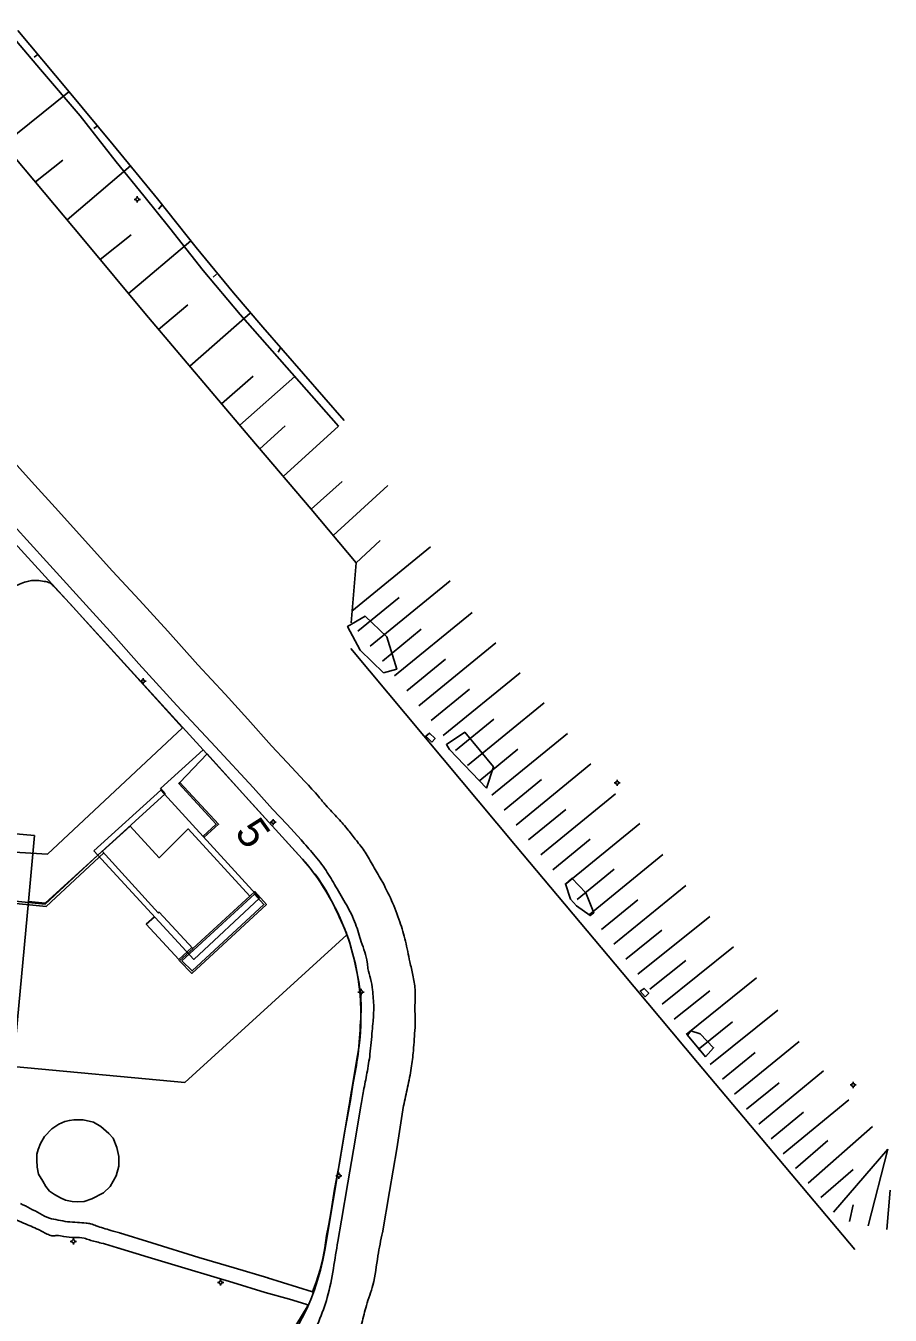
# Model space of a CAD drawing. Extents: x 1517229 to 1518128, y 6494851 to 6495271.
# Drawn here: x 1518015.9 to 1518128.2, y 6495054.4 to 6495221.8 of the extents above; entities that cross this region are included whole.
import ezdxf

# ---------------------------------------------------------------- set-up
doc = ezdxf.new("R2010")
doc.units = 0
doc.layers.add('Karta', color=7, linetype='Continuous')

msp = doc.modelspace()

# ---------------------------------------------------------------- linework, layer by layer
at = {"layer": 'Karta'}
for p, q in [((1518017.51, 6495218.07), (1518017.02, 6495217.73)), ((1518013.08, 6495206.44), (1518021.52, 6495213.26)), ((1518025.24, 6495208.83), (1518024.78, 6495208.5)), ((1518017.18, 6495201.54), (1518020.75, 6495204.36)), ((1518021.31, 6495196.6), (1518029.55, 6495203.63)), ((1518030.22, 6495199.28), (1518030.02, 6495199.28)), ((1518030.42, 6495199.48), (1518030.42, 6495199.68)), ((1518030.42, 6495199.08), (1518030.42, 6495198.88)), ((1518030.62, 6495199.28), (1518030.82, 6495199.28)), ((1518033.67, 6495198.57), (1518033.2, 6495198.02)), ((1518025.58, 6495191.49), (1518029.61, 6495194.69)), ((1518029.27, 6495187.04), (1518037.39, 6495193.88)), ((1518040.71, 6495189.56), (1518040.3, 6495189.16)), ((1518033.2, 6495182.37), (1518036.97, 6495185.57)), ((1518037.25, 6495177.6), (1518045.09, 6495184.52)), ((1518049, 6495179.92), (1518048.73, 6495179.42)), ((1518041.38, 6495172.72), (1518045.47, 6495176.34)), ((1518043.74, 6495169.94), (1518050.87, 6495176.26)), ((1518046.33, 6495166.89), (1518049.63, 6495169.88)), ((1518049.39, 6495163.29), (1518056.54, 6495169.83)), ((1518052.99, 6495159.05), (1518057.04, 6495162.64)), ((1518055.85, 6495155.65), (1518062.97, 6495162.11)), ((1518012.65, 6495156.65), (1518038.97, 6495127.79)), ((1518058.31, 6495145.79), (1518068.53, 6495154.15)), ((1518058.84, 6495152.1), (1518061.96, 6495155)), ((1518060.68, 6495141.26), (1518071.05, 6495149.75)), ((1518059.09, 6495143.2), (1518064.45, 6495147.58)), ((1518063.84, 6495137.39), (1518073.91, 6495145.63)), ((1518024.03, 6495144.16), (1518036.28, 6495130.66)), ((1518062.26, 6495139.33), (1518067.31, 6495143.46)), ((1518067, 6495133.52), (1518077.02, 6495141.71)), ((1518079.55, 6495115.38), (1518058.16, 6495140.96)), ((1518065.42, 6495135.46), (1518070.44, 6495139.56)), ((1518030.97, 6495136.71), (1518030.77, 6495136.71)), ((1518031.17, 6495136.91), (1518031.17, 6495137.11)), ((1518031.37, 6495136.71), (1518031.57, 6495136.71)), ((1518070.17, 6495129.65), (1518080.15, 6495137.81)), ((1518031.17, 6495136.51), (1518031.17, 6495136.31)), ((1518068.59, 6495131.59), (1518073.59, 6495135.68)), ((1518073.33, 6495125.78), (1518083.29, 6495133.92)), ((1518071.75, 6495127.72), (1518076.74, 6495131.79)), ((1518076.5, 6495121.91), (1518086.31, 6495129.93)), ((1518033.46, 6495122.76), (1518038.97, 6495127.79)), ((1518039.48, 6495127.28), (1518035.97, 6495123.55)), ((1518038.97, 6495127.79), (1518051.38, 6495114.18)), ((1518038.97, 6495127.79), (1518051.38, 6495114.18)), ((1518074.92, 6495123.84), (1518079.86, 6495127.89)), ((1518079.66, 6495118.04), (1518089.36, 6495125.97)), ((1518035.97, 6495123.55), (1518035.82, 6495123.4)), ((1518078.08, 6495119.97), (1518082.95, 6495123.95)), ((1518092.56, 6495123.52), (1518092.36, 6495123.52)), ((1518092.76, 6495123.72), (1518092.76, 6495123.92)), ((1518092.76, 6495123.32), (1518092.76, 6495123.12)), ((1518092.96, 6495123.52), (1518093.16, 6495123.52)), ((1518018.46, 6495107.89), (1518034.05, 6495122.11)), ((1518034.05, 6495122.11), (1518033.46, 6495122.76)), ((1518082.83, 6495114.17), (1518092.53, 6495122.1)), ((1518081.25, 6495116.1), (1518086.1, 6495120.07)), ((1517989.81, 6495119.18), (1518017.06, 6495116.66)), ((1518047.87, 6495118.42), (1518047.67, 6495118.42)), ((1518048.07, 6495118.62), (1518048.07, 6495118.82)), ((1518048.27, 6495118.42), (1518048.47, 6495118.42)), ((1518017.06, 6495116.66), (1518016.27, 6495108.09)), ((1518048.07, 6495118.22), (1518048.07, 6495118.02)), ((1518085.99, 6495110.3), (1518095.7, 6495118.24)), ((1518084.41, 6495112.23), (1518089.27, 6495116.2)), ((1518089.16, 6495106.43), (1518098.68, 6495114.21)), ((1518087.58, 6495108.36), (1518092.38, 6495112.29)), ((1518092.32, 6495102.56), (1518101.66, 6495110.19)), ((1518045.18, 6495108.64), (1518037.77, 6495101.82)), ((1518090.74, 6495104.49), (1518095.46, 6495108.34)), ((1518016.27, 6495108.09), (1518014.29, 6495086.68)), ((1518016.27, 6495108.09), (1518018.46, 6495107.89)), ((1518095.46, 6495098.66), (1518104.79, 6495106.15)), ((1518057.65, 6495103.8), (1518036.62, 6495084.62)), ((1518093.89, 6495100.61), (1518098.57, 6495104.37)), ((1518098.59, 6495094.76), (1518107.87, 6495102.21)), ((1518097.02, 6495096.71), (1518101.68, 6495100.45)), ((1518101.72, 6495090.86), (1518110.85, 6495098.19)), ((1518059.49, 6495096.55), (1518059.49, 6495096.75)), ((1518100.15, 6495092.81), (1518104.78, 6495096.53)), ((1518059.29, 6495096.35), (1518059.09, 6495096.35)), ((1518059.49, 6495096.15), (1518059.49, 6495095.95)), ((1518059.69, 6495096.35), (1518059.89, 6495096.35)), ((1518104.85, 6495086.96), (1518113.61, 6495094)), ((1518103.28, 6495088.91), (1518107.75, 6495092.5)), ((1518108, 6495083.08), (1518116.42, 6495089.94)), ((1518054.78, 6495062.83), (1518059.05, 6495088.13)), ((1518106.43, 6495085.02), (1518110.68, 6495088.49)), ((1518036.62, 6495084.62), (1518014.29, 6495086.68)), ((1518111.16, 6495079.21), (1518119.58, 6495086.13)), ((1518109.58, 6495081.15), (1518113.8, 6495084.58)), ((1518123.22, 6495084.29), (1518123.02, 6495084.29)), ((1518123.42, 6495084.49), (1518123.42, 6495084.69)), ((1518123.42, 6495084.09), (1518123.42, 6495083.89)), ((1518123.62, 6495084.29), (1518123.82, 6495084.29)), ((1518114.34, 6495075.35), (1518122.86, 6495082.35)), ((1518112.75, 6495077.28), (1518116.97, 6495080.75)), ((1518117.58, 6495071.54), (1518125.95, 6495078.88)), ((1518115.93, 6495073.42), (1518120.11, 6495077.08)), ((1518120.88, 6495067.78), (1518127.94, 6495075.97)), ((1518125.35, 6495065.98), (1518127.94, 6495075.97)), ((1518119.23, 6495069.66), (1518123.41, 6495073.33)), ((1518056.41, 6495072.5), (1518056.21, 6495072.5)), ((1518056.61, 6495072.7), (1518056.61, 6495072.9)), ((1518056.61, 6495072.3), (1518056.61, 6495072.1)), ((1518056.81, 6495072.5), (1518057.01, 6495072.5)), ((1518127.81, 6495065.54), (1518128.23, 6495070.62)), ((1518122.92, 6495066.55), (1518123.43, 6495068.71)), ((1518021.92, 6495063.98), (1518021.72, 6495063.98)), ((1518022.12, 6495064.18), (1518022.12, 6495064.38)), ((1518022.12, 6495063.78), (1518022.12, 6495063.58)), ((1518022.32, 6495063.98), (1518022.52, 6495063.98)), ((1518041.05, 6495058.64), (1518040.85, 6495058.64)), ((1518041.25, 6495058.84), (1518041.25, 6495059.04)), ((1518041.25, 6495058.44), (1518041.25, 6495058.24)), ((1518041.45, 6495058.64), (1518041.65, 6495058.64))]:
    msp.add_line(p, q, dxfattribs=at)
for points in [[(1518031.27, 6495199.75), (1518027.69, 6495204.15), (1518023.01, 6495210.11), (1518017.83, 6495216.14), (1518013.04, 6495221.82)], [(1518033.04, 6495199.36), (1518027.3, 6495206.38), (1518021.34, 6495213.48), (1518014.89, 6495221.21)], [(1518013.17, 6495206.32), (1518023.48, 6495194.01), (1518031.39, 6495184.5)], [(1518056.54, 6495169.83), (1518043.79, 6495184.31), (1518039, 6495190.03), (1518034.64, 6495195.53), (1518031.27, 6495199.75)], [(1518057.29, 6495170.56), (1518046.73, 6495182.68), (1518042.94, 6495187.12), (1518038.08, 6495193.01), (1518033.04, 6495199.36)], [(1518031.39, 6495184.5), (1518045.05, 6495168.4), (1518052.99, 6495159.05)], [(1518001.2, 6495171.42), (1518004.36, 6495167.91), (1518008.54, 6495163.33), (1518012.27, 6495159.23), (1518016.09, 6495155.08)], [(1518008.54, 6495171.61), (1518012.11, 6495167.69), (1518016.69, 6495162.63), (1518020.21, 6495158.78), (1518023.27, 6495155.38)], [(1518058.19, 6495144.3), (1518058.84, 6495152.1), (1518052.99, 6495159.05)], [(1518016.09, 6495155.08), (1518019.06, 6495151.77), (1518024.21, 6495146.11), (1518027.33, 6495142.68), (1518030.63, 6495138.98)], [(1518023.27, 6495155.38), (1518027.21, 6495151.02), (1518030.69, 6495147.23), (1518034.39, 6495143.2), (1518038.3, 6495138.86)], [(1518019.55, 6495149.06), (1518021.74, 6495146.7), (1518024.03, 6495144.16)], [(1518062.41, 6495137.8), (1518064.12, 6495138.29), (1518062.83, 6495142.46), (1518060.03, 6495145.15), (1518057.75, 6495143.82), (1518059.39, 6495140.75), (1518062.41, 6495137.8)], [(1518030.63, 6495138.98), (1518035.57, 6495133.58), (1518040.57, 6495128.19), (1518045.48, 6495122.91)], [(1518038.3, 6495138.86), (1518041.85, 6495135.01), (1518044.79, 6495131.8), (1518047.85, 6495128.31), (1518049.88, 6495126.16), (1518052.18, 6495123.7)], [(1518036.3, 6495130.68), (1518018.77, 6495114.27), (1518008.68, 6495114.85)], [(1518068.67, 6495128.78), (1518069.1, 6495129.26), (1518068.38, 6495129.98), (1518067.91, 6495129.58), (1518068.67, 6495128.78)], [(1518075.79, 6495122.82), (1518076.69, 6495125.6), (1518072.97, 6495130.09), (1518070.59, 6495128.49), (1518070.96, 6495127.84), (1518075.79, 6495122.82)], [(1518039.48, 6495127.28), (1518044.85, 6495121.32), (1518051.41, 6495114.14)], [(1518035.82, 6495123.41), (1518040.69, 6495118.14), (1518038.94, 6495116.57)], [(1518035.97, 6495123.55), (1518040.99, 6495118.13), (1518039.08, 6495116.42)], [(1518024.76, 6495114.7), (1518033.48, 6495122.56), (1518046.28, 6495108.54)], [(1518045.48, 6495122.91), (1518047.97, 6495120.09), (1518049.91, 6495118.09), (1518051.7, 6495116.12)], [(1518025.89, 6495114.63), (1518029.48, 6495117.89), (1518033.25, 6495113.79), (1518037.04, 6495117.54), (1518045.04, 6495108.81), (1518037.62, 6495101.99), (1518033.25, 6495106.71), (1518033.15, 6495106.63), (1518025.88, 6495114.63)], [(1518079.55, 6495115.38), (1518093.39, 6495098.88), (1518103.18, 6495087.2), (1518123.62, 6495062.93)], [(1518007.16, 6495108.89), (1518018.47, 6495107.78), (1518025.88, 6495114.63)], [(1518007.18, 6495108.58), (1518018.58, 6495107.47), (1518026.08, 6495114.41)], [(1518046.28, 6495108.54), (1518037.77, 6495100.58), (1518024.76, 6495114.7)], [(1518087.46, 6495107.53), (1518089.25, 6495106.28), (1518089.71, 6495106.65), (1518088.71, 6495109.22), (1518086.87, 6495111.13), (1518086.03, 6495110.41), (1518086.69, 6495108.4), (1518087.46, 6495107.53)], [(1518045.04, 6495108.81), (1518045.68, 6495109.39), (1518047.19, 6495107.71), (1518037.53, 6495098.78), (1518035.9, 6495100.41), (1518037.62, 6495101.98)], [(1518045.18, 6495108.64), (1518045.66, 6495109.07), (1518046.88, 6495107.72), (1518037.54, 6495099.09), (1518036.23, 6495100.4), (1518037.77, 6495101.82)], [(1518032.65, 6495106.13), (1518031.59, 6495105.15), (1518035.8, 6495100.57), (1518037.49, 6495102.13)], [(1518096.4, 6495095.71), (1518096.87, 6495096.22), (1518096.25, 6495096.83), (1518095.76, 6495096.48), (1518096.4, 6495095.71)], [(1518104.24, 6495087.96), (1518105.28, 6495089.11), (1518103.55, 6495090.92), (1518102.31, 6495091.3), (1518101.91, 6495090.74), (1518104.24, 6495087.96)], [(1518057.38, 6495078.31), (1518057.72, 6495080.2), (1518058.11, 6495082.29), (1518058.42, 6495084.3), (1518058.63, 6495085.47)], [(1518059.47, 6495081.53), (1518058.53, 6495075.86), (1518057.76, 6495071.6), (1518056.95, 6495066.72), (1518056.47, 6495063.97)], [(1518065.02, 6495081.61), (1518064.13, 6495076.01), (1518063.17, 6495070.45), (1518062.26, 6495065.1)], [(1518022.21, 6495079.78), (1518023.39, 6495079.78), (1518024.72, 6495079.45), (1518025.69, 6495078.9), (1518026.74, 6495078), (1518027.28, 6495077.4), (1518027.77, 6495076.16), (1518028.01, 6495074.98), (1518028.01, 6495073.74), (1518027.68, 6495072.47), (1518026.89, 6495071.11), (1518026.02, 6495070.27), (1518024.54, 6495069.51), (1518023.54, 6495069.15), (1518022.7, 6495069.12), (1518021.97, 6495069.15), (1518021.1, 6495069.33), (1518020.43, 6495069.61), (1518019.65, 6495070.06), (1518019.02, 6495070.48), (1518018.53, 6495071.11), (1518018.14, 6495071.81), (1518017.6, 6495072.72), (1518017.42, 6495073.62), (1518017.36, 6495074.53), (1518017.36, 6495075.31), (1518017.54, 6495075.89), (1518017.87, 6495076.7), (1518018.35, 6495077.58), (1518019.32, 6495078.57), (1518020.25, 6495079.21), (1518021.01, 6495079.54), (1518021.61, 6495079.69), (1518022.18, 6495079.78), (1518022.18, 6495079.78)], [(1518055.6, 6495067.93), (1518056.02, 6495070.76), (1518056.67, 6495074.12), (1518057.07, 6495076.57), (1518057.38, 6495078.31)], [(1518047.34, 6495059.26), (1518053.17, 6495057.42), (1518053.67, 6495058.69), (1518054.2, 6495060.31), (1518054.54, 6495061.74), (1518054.79, 6495063.14), (1518055.01, 6495064.76), (1518055.32, 6495066.22), (1518055.6, 6495067.93)], [(1518028.11, 6495065.09), (1518032.32, 6495063.79), (1518038.41, 6495061.9), (1518043.01, 6495060.56), (1518047.36, 6495059.25)], [(1518027.72, 6495063.19), (1518031.82, 6495061.93), (1518037.04, 6495060.37), (1518042.85, 6495058.63), (1518047.05, 6495057.36)], [(1518047.05, 6495057.36), (1518050.19, 6495056.46), (1518052.3, 6495055.83), (1518052.64, 6495055.68), (1518051.87, 6495054.47), (1518051.15, 6495053.28), (1518050.38, 6495052.07), (1518049.57, 6495050.61), (1518048.73, 6495049.65), (1518047.98, 6495048.5), (1518047.11, 6495047.69)]]:
    msp.add_lwpolyline(points, dxfattribs=at)
for centre in [(1518030.42, 6495199.28), (1518031.17, 6495136.71), (1518092.76, 6495123.52), (1518048.07, 6495118.42), (1518059.49, 6495096.35), (1518123.42, 6495084.29), (1518056.61, 6495072.5), (1518022.12, 6495063.98), (1518041.25, 6495058.64)]:
    msp.add_circle(centre, 0.2, dxfattribs=at)
for centre, radius, start, end in [((1518028.46, 6495093.28), 31.02, 19.8209, 42.3652), ((1518028.46, 6495093.28), 31.02, 19.8209, 42.3652), ((1518028.47, 6495093.29), 31.01, 350.4256, 19.8012), ((1518025.19, 6495067.83), 30.01, 309.8505, 350.4132)]:
    msp.add_arc(centre, radius, start, end, dxfattribs=at)
for points in [[(1518012.69, 6495147.54), (1518014.35, 6495148.9), (1518015.98, 6495149.62), (1518017.39, 6495149.81), (1518018.33, 6495149.68), (1518019.08, 6495149.47), (1518019.56, 6495149.05)], [(1518052.18, 6495123.7), (1518054, 6495121.7), (1518054.91, 6495120.61), (1518056.52, 6495118.88), (1518057.82, 6495117.39), (1518058.88, 6495116.03), (1518060.03, 6495114.51), (1518061.06, 6495112.73), (1518062.12, 6495110.91), (1518063.46, 6495108.24)], [(1518051.7, 6495116.12), (1518053.33, 6495114.24), (1518054.94, 6495112.15), (1518056.21, 6495110.03), (1518057.61, 6495107.66)], [(1518051.41, 6495114.14), (1518054.63, 6495110.05), (1518056.65, 6495106.12), (1518057.65, 6495103.82), (1518058.89, 6495099.17), (1518059.45, 6495095.75), (1518059.39, 6495091.99)], [(1518063.45, 6495108.26), (1518064.53, 6495105.48), (1518065.26, 6495102.96), (1518065.83, 6495100.29), (1518066.23, 6495098.54), (1518066.5, 6495096.69), (1518066.5, 6495094.99), (1518066.5, 6495093.47), (1518066.5, 6495091.59)], [(1518057.61, 6495107.66), (1518058.77, 6495105.21), (1518059.52, 6495102.86), (1518060.3, 6495100.21), (1518060.38, 6495099.41), (1518060.73, 6495098.09), (1518060.97, 6495096.64), (1518061.14, 6495094.41), (1518061.05, 6495092.56), (1518060.93, 6495091.29)], [(1518059.39, 6495091.99), (1518059.03, 6495087.73), (1518058.36, 6495084.09), (1518057.85, 6495081)], [(1518066.5, 6495091.74), (1518066.29, 6495088.74), (1518066.02, 6495086.47), (1518065.53, 6495084.01), (1518065.02, 6495081.59)], [(1518060.93, 6495091.32), (1518060.65, 6495088.29), (1518060.26, 6495085.83), (1518059.81, 6495083.53), (1518059.47, 6495081.53)], [(1518027.99, 6495063.11), (1518025.73, 6495063.76), (1518024.2, 6495064.17), (1518023.52, 6495064.38), (1518022.28, 6495064.48), (1518020.88, 6495064.6), (1518019.98, 6495064.73), (1518019.48, 6495064.7), (1518018.89, 6495064.85), (1518017.58, 6495065.5), (1518015.66, 6495066.34), (1518013.29, 6495067.34), (1518012.27, 6495067.65), (1518011.74, 6495067.8), (1518011.15, 6495067.74), (1518009.78, 6495067.59), (1518008.51, 6495067.43), (1518006.92, 6495067.24), (1518005.49, 6495067.06), (1518004.28, 6495067.15), (1518003.29, 6495067.43), (1518002.29, 6495067.62), (1518001.86, 6495067.96), (1518001.17, 6495068.64), (1518000.8, 6495068.99), (1518000.37, 6495069.54)], [(1518015.25, 6495068.89), (1518017.77, 6495067.59), (1518019.01, 6495067), (1518020.13, 6495066.75), (1518021.34, 6495066.53), (1518022.65, 6495066.44), (1518023.77, 6495066.34), (1518024.36, 6495066.25), (1518025.1, 6495066), (1518026.97, 6495065.41), (1518028.31, 6495065.04)], [(1518062.27, 6495065.15), (1518061.68, 6495062.09), (1518061.03, 6495058.31), (1518060.18, 6495055.65), (1518059.6, 6495053.37), (1518058.88, 6495050.96), (1518057.71, 6495048.16), (1518056.15, 6495045.42), (1518054.85, 6495043.34), (1518053.09, 6495040.93), (1518051.14, 6495038.33), (1518049.51, 6495036.57), (1518047.82, 6495034.88), (1518046.65, 6495033.51)], [(1518056.47, 6495063.98), (1518055.89, 6495060.46), (1518055.11, 6495056.69), (1518054, 6495053.56), (1518052.76, 6495050.63), (1518051.79, 6495048.75), (1518050.68, 6495046.79), (1518049.38, 6495044.64), (1518047.63, 6495042.37), (1518046.26, 6495040.67), (1518045.15, 6495039.57), (1518044.24, 6495038.52), (1518043.02, 6495037.6)]]:
    msp.add_spline(points, degree=3, dxfattribs=at)

# ---------------------------------------------------------------- texts
msp.add_text('5', height=4, rotation=305.5194, dxfattribs=at).set_placement((1518042.98, 6495117.08))

doc.saveas('drawing.dxf')
